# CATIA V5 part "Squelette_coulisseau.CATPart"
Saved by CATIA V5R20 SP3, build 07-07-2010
Part number: Squelette_coulisseau
Publications: "Plan.1", "Plan.2", "Point.1", "Droite.1"
Bounding box of the stored display mesh (mm): x 0 to 0, y -10 to 10, z 0 to 0
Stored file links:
  C:\Documents and Settings\Propriétaire\Mes documents\IFMA\COURS\PROJ IAO\CATIA\Squelette_coulisseau.CATPart
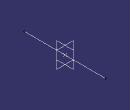
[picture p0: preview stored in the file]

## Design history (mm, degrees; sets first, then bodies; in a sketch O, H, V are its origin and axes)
Set1
  Plane1: type Offset, RefPlane zx-plane, Offset 0
  Plane2: type Offset, RefPlane yz-plane, Offset 0
  Point1: (0, 0, 0)
  Line1: type PtDir, RefPoint Point1, Direction Plane1, Start -10, End 10
Body1 (main body)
